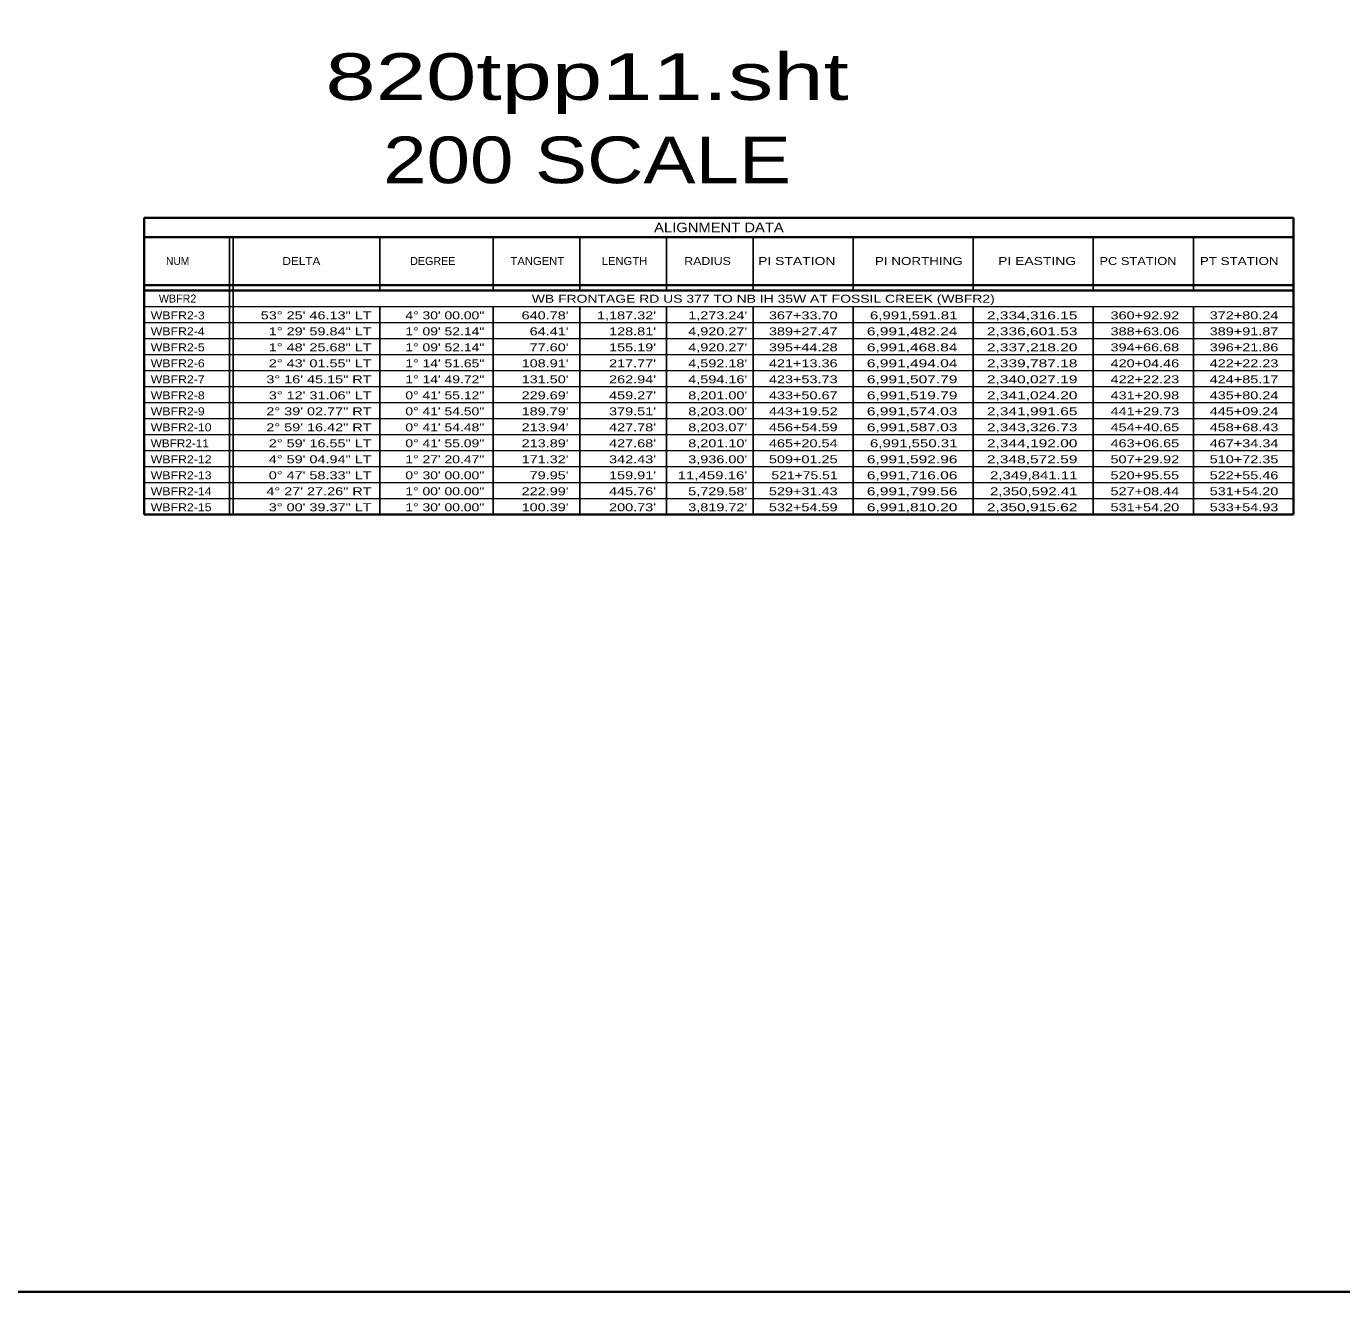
# Model space of a CAD drawing. Extents: x 1953053 to 1967065, y 7363860 to 7371201.
# Drawn here: x 1961790 to 1963762, y 7363860 to 7365759 of the extents above; entities that cross this region are included whole.
import ezdxf
from ezdxf.enums import TextEntityAlignment as Align

# ---------------------------------------------------------------- set-up
doc = ezdxf.new("R2010")
doc.units = 0
doc.header["$LTSCALE"] = 4.8
doc.layers.add('10', color=7, linetype='Continuous')
doc.layers.add('12', color=7, linetype='Continuous', lineweight=25)
doc.layers.add('62', color=7, linetype='Continuous', lineweight=35)

msp = doc.modelspace()

# ---------------------------------------------------------------- linework, layer by layer
at = {"layer": '12', "lineweight": 35}
for p, q in [((1963689.794, 7365471.266), (1961966.462, 7365471.266)), ((1961966.462, 7365471.266), (1961966.462, 7365026.133)), ((1963689.794, 7365026.133), (1963689.794, 7365471.266)), ((1961966.462, 7365442.466), (1963689.794, 7365442.466)), ((1961966.462, 7365370.466), (1963689.794, 7365370.466)), ((1961966.462, 7365362.133), (1963689.794, 7365362.133)), ((1961966.462, 7365026.133), (1963689.794, 7365026.133))]:
    msp.add_line(p, q, dxfattribs=at)
at = {"layer": '12'}
for p, q in [((1962094.307, 7365442.466), (1962094.307, 7365026.133)), ((1962099.794, 7365442.466), (1962099.794, 7365026.133)), ((1962319.794, 7365442.466), (1962319.794, 7365362.133)), ((1962489.794, 7365442.466), (1962489.794, 7365362.133)), ((1962619.794, 7365442.466), (1962619.794, 7365362.133)), ((1962749.794, 7365442.466), (1962749.794, 7365362.133)), ((1962879.794, 7365442.466), (1962879.794, 7365362.133)), ((1963029.794, 7365442.466), (1963029.794, 7365362.133)), ((1963209.794, 7365442.466), (1963209.794, 7365362.133)), ((1963389.794, 7365442.466), (1963389.794, 7365362.133)), ((1963539.794, 7365442.466), (1963539.794, 7365362.133)), ((1962094.307, 7365420.866), (1962094.307, 7365144.913)), ((1962319.794, 7365338.133), (1962319.794, 7365026.133)), ((1962489.794, 7365338.133), (1962489.794, 7365026.133)), ((1962619.794, 7365338.133), (1962619.794, 7365026.133)), ((1962749.794, 7365338.133), (1962749.794, 7365026.133)), ((1962879.794, 7365338.133), (1962879.794, 7365026.133)), ((1963029.794, 7365338.133), (1963029.794, 7365026.133)), ((1963209.794, 7365338.133), (1963209.794, 7365026.133)), ((1963389.794, 7365338.133), (1963389.794, 7365026.133)), ((1963539.794, 7365338.133), (1963539.794, 7365026.133))]:
    msp.add_line(p, q, dxfattribs=at)
at = {"layer": '12', "lineweight": 13}
for p, q in [((1961966.462, 7365338.133), (1963689.794, 7365338.133)), ((1961966.462, 7365314.133), (1963689.794, 7365314.133)), ((1961966.462, 7365290.133), (1963689.794, 7365290.133)), ((1961966.462, 7365266.133), (1963689.794, 7365266.133)), ((1961966.462, 7365242.133), (1963689.794, 7365242.133)), ((1961966.462, 7365218.133), (1963689.794, 7365218.133)), ((1961966.462, 7365194.133), (1963689.794, 7365194.133)), ((1961966.462, 7365170.133), (1963689.794, 7365170.133)), ((1961966.462, 7365146.133), (1963689.794, 7365146.133)), ((1961966.462, 7365122.133), (1963689.794, 7365122.133)), ((1961966.462, 7365098.133), (1963689.794, 7365098.133)), ((1961966.462, 7365074.133), (1963689.794, 7365074.133)), ((1961966.462, 7365050.133), (1963689.794, 7365050.133))]:
    msp.add_line(p, q, dxfattribs=at)
at = {"layer": '62'}
msp.add_lwpolyline([(1953052.784, 7371201.108), (1967065.314, 7371201.108), (1967065.314, 7363859.877), (1953052.784, 7363859.877)], close=True, dxfattribs=at)

# ---------------------------------------------------------------- texts
at = {"layer": '10'}
msp.add_text('WBFR2', height=12, dxfattribs=at).set_placement((1961988.304, 7365344.176))
at = {"layer": '10', "width": 1.3}
msp.add_text('WB FRONTAGE RD US 377 TO NB IH 35W AT FOSSIL CREEK (WBFR2)', height=12, dxfattribs=at).set_placement((1962894.794, 7365343.927), align=Align.CENTER)
at = {"layer": '10'}
for s, width, p in [('WBFR2-3', 1.15, (1961976.083, 7365318.96)), ('WBFR2-4', 1.15, (1961976.083, 7365294.96)), ('WBFR2-5', 1.15, (1961976.083, 7365270.96)), ('WBFR2-6', 1.15, (1961976.083, 7365246.96)), ('WBFR2-7', 1.15, (1961976.083, 7365222.96)), ('WBFR2-8', 1.15, (1961976.083, 7365198.96)), ('WBFR2-9', 1.15, (1961976.083, 7365174.96)), ('WBFR2-10', 1.15, (1961976.083, 7365150.96)), ('WBFR2-11', 1.1, (1961976.083, 7365126.96)), ('WBFR2-12', 1.15, (1961976.083, 7365102.96)), ('WBFR2-13', 1.15, (1961976.083, 7365078.96)), ('WBFR2-14', 1.15, (1961976.083, 7365054.96)), ('WBFR2-15', 1.15, (1961976.083, 7365030.96))]:
    msp.add_text(s, height=12, dxfattribs=dict(at, width=width)).set_placement(p)
for s, width, p in [('53° 25\' 46.13" LT', 1.35, (1962307.316, 7365318.96)), ('4° 30\' 00.00"', 1.3, (1962476.311, 7365318.96)), ("640.78'", 1.35, (1962602.721, 7365318.96)), ("1,187.32'", 1.35, (1962733.918, 7365318.96)), ("1,273.24'", 1.35, (1962870.687, 7365318.96)), ('367+33.70', 1.35, (1963006.231, 7365318.96)), ('6,991,591.81', 1.4, (1963185.996, 7365318.96)), ('2,334,316.15', 1.45, (1963365.996, 7365318.96)), ('360+92.92', 1.35, (1963518.574, 7365318.96)), ('372+80.24', 1.35, (1963667.306, 7365318.96)), ('1° 29\' 59.84" LT', 1.35, (1962307.316, 7365294.96)), ('1° 09\' 52.14"', 1.3, (1962476.311, 7365294.96)), ("64.41'", 1.35, (1962602.721, 7365294.96)), ("128.81'", 1.35, (1962733.918, 7365294.96)), ("4,920.27'", 1.35, (1962870.687, 7365294.96)), ('389+27.47', 1.35, (1963006.231, 7365294.96)), ('6,991,482.24', 1.45, (1963185.996, 7365294.96)), ('2,336,601.53', 1.45, (1963365.996, 7365294.96)), ('388+63.06', 1.35, (1963518.574, 7365294.96)), ('389+91.87', 1.35, (1963667.306, 7365294.96)), ('1° 48\' 25.68" LT', 1.35, (1962307.316, 7365270.96)), ('1° 09\' 52.14"', 1.3, (1962476.311, 7365270.96)), ("77.60'", 1.35, (1962602.721, 7365270.96)), ("155.19'", 1.35, (1962733.918, 7365270.96)), ("4,920.27'", 1.35, (1962870.687, 7365270.96)), ('395+44.28', 1.35, (1963006.231, 7365270.96)), ('6,991,468.84', 1.45, (1963185.996, 7365270.96)), ('2,337,218.20', 1.45, (1963365.996, 7365270.96)), ('394+66.68', 1.35, (1963518.574, 7365270.96)), ('396+21.86', 1.35, (1963667.306, 7365270.96)), ('2° 43\' 01.55" LT', 1.35, (1962307.316, 7365246.96)), ('1° 14\' 51.65"', 1.3, (1962476.311, 7365246.96)), ("108.91'", 1.35, (1962602.721, 7365246.96)), ("217.77'", 1.35, (1962733.918, 7365246.96)), ("4,592.18'", 1.35, (1962870.687, 7365246.96)), ('421+13.36', 1.35, (1963006.231, 7365246.96)), ('6,991,494.04', 1.45, (1963185.996, 7365246.96)), ('2,339,787.18', 1.45, (1963365.996, 7365246.96)), ('420+04.46', 1.35, (1963518.574, 7365246.96)), ('422+22.23', 1.35, (1963667.306, 7365246.96)), ('3° 16\' 45.15" RT', 1.35, (1962307.316, 7365222.96)), ('1° 14\' 49.72"', 1.3, (1962476.311, 7365222.96)), ("131.50'", 1.35, (1962602.721, 7365222.96)), ("262.94'", 1.35, (1962733.918, 7365222.96)), ("4,594.16'", 1.35, (1962870.687, 7365222.96)), ('423+53.73', 1.35, (1963006.231, 7365222.96)), ('6,991,507.79', 1.45, (1963185.996, 7365222.96)), ('2,340,027.19', 1.45, (1963365.996, 7365222.96)), ('422+22.23', 1.35, (1963518.574, 7365222.96)), ('424+85.17', 1.35, (1963667.306, 7365222.96)), ('3° 12\' 31.06" LT', 1.35, (1962307.316, 7365198.96)), ('0° 41\' 55.12"', 1.3, (1962476.311, 7365198.96)), ("229.69'", 1.35, (1962602.721, 7365198.96)), ("459.27'", 1.35, (1962733.918, 7365198.96)), ("8,201.00'", 1.35, (1962870.687, 7365198.96)), ('433+50.67', 1.35, (1963006.231, 7365198.96)), ('6,991,519.79', 1.45, (1963185.996, 7365198.96)), ('2,341,024.20', 1.45, (1963365.996, 7365198.96)), ('431+20.98', 1.35, (1963518.574, 7365198.96)), ('435+80.24', 1.35, (1963667.306, 7365198.96)), ('2° 39\' 02.77" RT', 1.35, (1962307.316, 7365174.96)), ('0° 41\' 54.50"', 1.3, (1962476.311, 7365174.96)), ("189.79'", 1.35, (1962602.721, 7365174.96)), ("379.51'", 1.35, (1962733.918, 7365174.96)), ("8,203.00'", 1.35, (1962870.687, 7365174.96)), ('443+19.52', 1.35, (1963006.231, 7365174.96)), ('6,991,574.03', 1.45, (1963185.996, 7365174.96)), ('2,341,991.65', 1.45, (1963365.996, 7365174.96)), ('441+29.73', 1.35, (1963518.574, 7365174.96)), ('445+09.24', 1.35, (1963667.306, 7365174.96)), ('2° 59\' 16.42" RT', 1.35, (1962307.316, 7365150.96)), ('0° 41\' 54.48"', 1.3, (1962476.311, 7365150.96)), ("213.94'", 1.35, (1962602.721, 7365150.96)), ("427.78'", 1.35, (1962733.918, 7365150.96)), ("8,203.07'", 1.35, (1962870.687, 7365150.96)), ('456+54.59', 1.35, (1963006.231, 7365150.96)), ('6,991,587.03', 1.45, (1963185.996, 7365150.96)), ('2,343,326.73', 1.45, (1963365.996, 7365150.96)), ('454+40.65', 1.35, (1963518.574, 7365150.96)), ('458+68.43', 1.35, (1963667.306, 7365150.96)), ('2° 59\' 16.55" LT', 1.35, (1962307.316, 7365126.96)), ('0° 41\' 55.09"', 1.3, (1962476.311, 7365126.96)), ("213.89'", 1.35, (1962602.721, 7365126.96)), ("427.68'", 1.35, (1962733.918, 7365126.96)), ("8,201.10'", 1.35, (1962870.687, 7365126.96)), ('465+20.54', 1.35, (1963006.231, 7365126.96)), ('6,991,550.31', 1.4, (1963185.996, 7365126.96)), ('2,344,192.00', 1.45, (1963365.996, 7365126.96)), ('463+06.65', 1.35, (1963518.574, 7365126.96)), ('467+34.34', 1.35, (1963667.306, 7365126.96)), ('4° 59\' 04.94" LT', 1.35, (1962307.316, 7365102.96)), ('1° 27\' 20.47"', 1.3, (1962476.311, 7365102.96)), ("171.32'", 1.35, (1962602.721, 7365102.96)), ("342.43'", 1.35, (1962733.918, 7365102.96)), ("3,936.00'", 1.35, (1962870.687, 7365102.96)), ('509+01.25', 1.35, (1963006.231, 7365102.96)), ('6,991,592.96', 1.45, (1963185.996, 7365102.96)), ('2,348,572.59', 1.45, (1963365.996, 7365102.96)), ('507+29.92', 1.35, (1963518.574, 7365102.96)), ('510+72.35', 1.35, (1963667.306, 7365102.96)), ('0° 47\' 58.33" LT', 1.35, (1962307.316, 7365078.96)), ('0° 30\' 00.00"', 1.3, (1962476.311, 7365078.96)), ("79.95'", 1.35, (1962602.721, 7365078.96)), ("159.91'", 1.35, (1962733.918, 7365078.96)), ("11,459.16'", 1.4, (1962870.687, 7365078.96)), ('521+75.51', 1.3, (1963006.231, 7365078.96)), ('6,991,716.06', 1.45, (1963185.996, 7365078.96)), ('2,349,841.11', 1.4, (1963365.996, 7365078.96)), ('520+95.55', 1.35, (1963518.574, 7365078.96)), ('522+55.46', 1.35, (1963667.306, 7365078.96)), ('4° 27\' 27.26" RT', 1.35, (1962307.316, 7365054.96)), ('1° 00\' 00.00"', 1.3, (1962476.311, 7365054.96)), ("222.99'", 1.35, (1962602.721, 7365054.96)), ("445.76'", 1.35, (1962733.918, 7365054.96)), ("5,729.58'", 1.35, (1962870.687, 7365054.96)), ('529+31.43', 1.35, (1963006.231, 7365054.96)), ('6,991,799.56', 1.45, (1963185.996, 7365054.96)), ('2,350,592.41', 1.4, (1963365.996, 7365054.96)), ('527+08.44', 1.35, (1963518.574, 7365054.96)), ('531+54.20', 1.35, (1963667.306, 7365054.96)), ('3° 00\' 39.37" LT', 1.35, (1962307.316, 7365030.96)), ('1° 30\' 00.00"', 1.3, (1962476.311, 7365030.96)), ("100.39'", 1.35, (1962602.721, 7365030.96)), ("200.73'", 1.35, (1962733.918, 7365030.96)), ("3,819.72'", 1.35, (1962870.687, 7365030.96)), ('532+54.59', 1.35, (1963006.231, 7365030.96)), ('6,991,810.20', 1.45, (1963185.996, 7365030.96)), ('2,350,915.62', 1.45, (1963365.996, 7365030.96)), ('531+54.20', 1.35, (1963518.574, 7365030.96)), ('533+54.93', 1.35, (1963667.306, 7365030.96))]:
    msp.add_text(s, height=12, dxfattribs=dict(at, width=width)).set_placement(p, align=Align.RIGHT)
at = {"layer": '12'}
for s, height, width, p in [('ALIGNMENT DATA', 14.4, 1.15, (1962828.235, 7365449.665)), ('NUM', 12, 0.95, (1962016.508, 7365400.462)), ('DELTA', 12, 1.1, (1962202.085, 7365400.465)), ('TANGENT', 12, 1.05, (1962555.982, 7365400.465)), ('LENGTH', 12, 1.05, (1962686.617, 7365400.465)), ('RADIUS', 12, 1.15, (1962811.227, 7365400.465)), ('PI STATION', 12, 1.3, (1962945.031, 7365400.465)), ('PI NORTHING', 12, 1.25, (1963128.106, 7365400.465)), ('PI EASTING', 12, 1.3, (1963305.498, 7365400.465)), ('PC STATION', 12, 1.2, (1963456.803, 7365400.465)), ('PT STATION', 12, 1.25, (1963608.574, 7365400.465))]:
    msp.add_text(s, height=height, dxfattribs=dict(at, width=width)).set_placement(p, align=Align.CENTER)
msp.add_text('DEGREE', height=12, dxfattribs=at).set_placement((1962399.171, 7365400.465), align=Align.CENTER)
at = {"layer": '62'}
for s, width, p in [('820tpp11.sht', 1.45, (1962630.518, 7365648.265)), ('200 SCALE', 1.25, (1962630.518, 7365523.265))]:
    msp.add_text(s, height=70, dxfattribs=dict(at, width=width)).set_placement(p, align=Align.CENTER)

doc.saveas('drawing.dxf')
